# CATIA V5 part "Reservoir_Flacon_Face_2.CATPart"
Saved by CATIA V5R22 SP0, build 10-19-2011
Part number: Reservoir_Flacon_Face
Bounding box of the stored display mesh (mm): x -31 to 31, y 0 to 5, z -112.5 to 112.5
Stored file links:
  D:\PER\CAO_PER_MODIF_2025\CAO_PER_pick&place_2024P\Sous_Ensemble_Flacon\Reservoir_Flacon_Face_2.CATPart
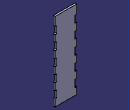
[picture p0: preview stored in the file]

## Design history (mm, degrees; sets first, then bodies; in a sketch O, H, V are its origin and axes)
Body1 (main body)
  Sketch1 on zx-plane, origin (0, 0, 0), H (-1, 0, 0), V (0, 0, 1)
    line L1 (-31, 112.5) -> (31, 112.5)
    line L2 (31, 112.5) -> (31, -112.5)
    line L3 (31, -112.5) -> (-31, -112.5)
    line L4 (-31, -112.5) -> (-31, 112.5)
    length L4 = 225
    length L1 = 62
    horizontal: L1 H, L3 H
    vertical: L2 V, L4 V
    symmetry: L4 L2 V, L1 L3 H
  Pad1: profile Sketch1, direction (0, 1, 0), length 5
  Sketch2 on end face of Pad1, origin (0, 5, 0), H (-1, 0, 0), V (0, 0, 1)
    point P1 (-31, 87.5)
    line L1 (-31, 87.5) -> (-26, 87.5)
    line L2 (-26, 87.5) -> (-26, 67.5)
    line L3 (-26, 67.5) -> (-31, 67.5)
    line L4 (-31, 67.5) -> (-31, 87.5)
    point P2 (-26, 87.5)
    point P3 (-26, 67.5)
    point P4 (-31, 67.5)
    reference projected line E1 (-31, 112.5) -> (-31, -112.5) from edge [face of Pad1 from Sketch1.L4 | end face of Pad1]
    reference projected line E2 (31, 112.5) -> (-31, 112.5) from edge [face of Pad1 from Sketch1.L1 | end face of Pad1]
    point P5 (31, 87.5)
    point P6 (26, 87.5)
    point P7 (26, 67.5)
    point P8 (31, 67.5)
    line L5 (31, 87.5) -> (26, 87.5)
    line L6 (26, 87.5) -> (26, 67.5)
    line L7 (26, 67.5) -> (31, 67.5)
    line L8 (31, 67.5) -> (31, 87.5)
    distance L1 E2 = 25
    length L4 = 20
    length L1 = 5
    horizontal: L1 H, L3 H
    vertical: L2 V, L4 V
    coincidence: L4 E1
    symmetry: P1 P5 V, P2 P6 V, P3 P7 V, P4 P8 V, L1 L5 V, L2 L6 V, L3 L7 V, L4 L8 V
  Pocket1: profile Sketch2, direction (0, -1, 0), through (limit type 6)
  RectPattern1: of Pocket1, direction 1 instances 5, spacing 40, along edge [face of Pad1 from Sketch1.L4 | end face of Pad1]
